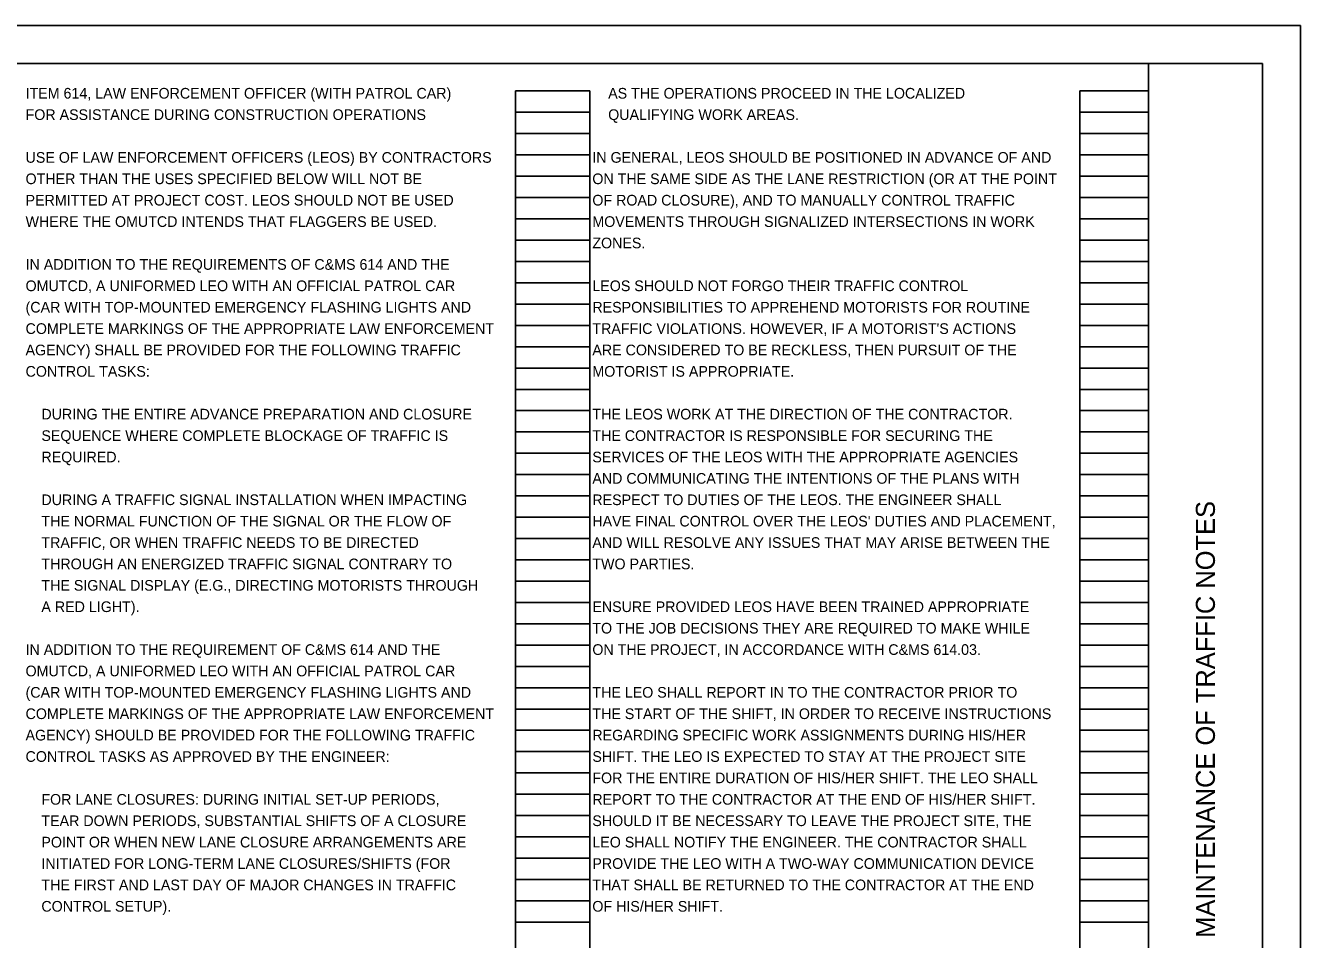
# Model space of a CAD drawing. Extents: x 0 to 34, y 0 to 22.
# Drawn here: x 17.24 to 34, y 9.99 to 22 of the extents above; entities that cross this region are included whole.
import ezdxf

# ---------------------------------------------------------------- set-up
doc = ezdxf.new("R2010")
doc.units = 0
for name, color, linetype in [('SH_Border', 7, 'Continuous'), ('SH_Cut_Line', 7, 'Continuous'), ('SH_Data', 7, 'Continuous'), ('TX_P_1', 7, 'Continuous')]:
    doc.layers.add(name, color=color, linetype=linetype)

msp = doc.modelspace()

# ---------------------------------------------------------------- linework, layer by layer
at = {"layer": 'SH_Border'}
msp.add_line((32, 0.5), (32, 21.5), dxfattribs=at)
msp.add_lwpolyline([(1.5, 21.5), (33.5, 21.5), (33.5, 0.5), (1.5, 0.5)], close=True, dxfattribs=at)
at = {"layer": 'SH_Cut_Line'}
msp.add_lwpolyline([(0, 0), (34, 0), (34, 22), (0, 22)], close=True, dxfattribs=at)
at = {"layer": 'SH_Data'}
for p, q in [((23.68, 0.98), (23.68, 21.14)), ((23.68, 21.14), (24.66, 21.14)), ((24.66, 0.98), (24.66, 21.14)), ((31.1, 0.98), (31.1, 21.14)), ((31.1, 21.14), (32, 21.14)), ((32, 0.98), (32, 21.14)), ((23.68, 20.86), (24.66, 20.86)), ((31.1, 20.86), (32, 20.86)), ((23.68, 20.58), (24.66, 20.58)), ((31.1, 20.58), (32, 20.58)), ((23.68, 20.3), (24.66, 20.3)), ((31.1, 20.3), (32, 20.3)), ((23.68, 20.02), (24.66, 20.02)), ((31.1, 20.02), (32, 20.02)), ((23.68, 19.74), (24.66, 19.74)), ((31.1, 19.74), (32, 19.74)), ((23.68, 19.46), (24.66, 19.46)), ((31.1, 19.46), (32, 19.46)), ((23.68, 19.18), (24.66, 19.18)), ((31.1, 19.18), (32, 19.18)), ((23.68, 18.9), (24.66, 18.9)), ((31.1, 18.9), (32, 18.9)), ((23.68, 18.62), (24.66, 18.62)), ((31.1, 18.62), (32, 18.62)), ((23.68, 18.34), (24.66, 18.34)), ((31.1, 18.34), (32, 18.34)), ((23.68, 18.06), (24.66, 18.06)), ((31.1, 18.06), (32, 18.06)), ((23.68, 17.78), (24.66, 17.78)), ((31.1, 17.78), (32, 17.78)), ((23.68, 17.5), (24.66, 17.5)), ((31.1, 17.5), (32, 17.5)), ((23.68, 17.22), (24.66, 17.22)), ((31.1, 17.22), (32, 17.22)), ((23.68, 16.94), (24.66, 16.94)), ((31.1, 16.94), (32, 16.94)), ((23.68, 16.66), (24.66, 16.66)), ((31.1, 16.66), (32, 16.66)), ((23.68, 16.38), (24.66, 16.38)), ((31.1, 16.38), (32, 16.38)), ((23.68, 16.1), (24.66, 16.1)), ((31.1, 16.1), (32, 16.1)), ((23.68, 15.82), (24.66, 15.82)), ((31.1, 15.82), (32, 15.82)), ((23.68, 15.54), (24.66, 15.54)), ((31.1, 15.54), (32, 15.54)), ((23.68, 15.26), (24.66, 15.26)), ((31.1, 15.26), (32, 15.26)), ((23.68, 14.98), (24.66, 14.98)), ((31.1, 14.98), (32, 14.98)), ((23.68, 14.7), (24.66, 14.7)), ((31.1, 14.7), (32, 14.7)), ((23.68, 14.42), (24.66, 14.42)), ((31.1, 14.42), (32, 14.42)), ((23.68, 14.14), (24.66, 14.14)), ((31.1, 14.14), (32, 14.14)), ((23.68, 13.86), (24.66, 13.86)), ((31.1, 13.86), (32, 13.86)), ((23.68, 13.58), (24.66, 13.58)), ((31.1, 13.58), (32, 13.58)), ((23.68, 13.3), (24.66, 13.3)), ((31.1, 13.3), (32, 13.3)), ((23.68, 13.02), (24.66, 13.02)), ((31.1, 13.02), (32, 13.02)), ((23.68, 12.74), (24.66, 12.74)), ((31.1, 12.74), (32, 12.74)), ((23.68, 12.46), (24.66, 12.46)), ((31.1, 12.46), (32, 12.46)), ((23.68, 12.18), (24.66, 12.18)), ((31.1, 12.18), (32, 12.18)), ((23.68, 11.9), (24.66, 11.9)), ((31.1, 11.9), (32, 11.9)), ((23.68, 11.62), (24.66, 11.62)), ((31.1, 11.62), (32, 11.62)), ((23.68, 11.34), (24.66, 11.34)), ((31.1, 11.34), (32, 11.34)), ((23.68, 11.06), (24.66, 11.06)), ((31.1, 11.06), (32, 11.06)), ((23.68, 10.78), (24.66, 10.78)), ((31.1, 10.78), (32, 10.78)), ((23.68, 10.5), (24.66, 10.5)), ((31.1, 10.5), (32, 10.5)), ((23.68, 10.22), (24.66, 10.22)), ((31.1, 10.22), (32, 10.22))]:
    msp.add_line(p, q, dxfattribs=at)

# ---------------------------------------------------------------- texts
msp.add_text('MAINTENANCE OF TRAFFIC NOTES', height=0.25, rotation=90, dxfattribs=at).set_placement((32.875, 10.014))
at = {"layer": 'TX_P_1'}
for s, p in [('ITEM 614, LAW ENFORCEMENT OFFICER (WITH PATROL CAR)', (17.242, 21.04)), ('    AS THE OPERATIONS PROCEED IN THE LOCALIZED', (24.692, 21.04)), ('FOR ASSISTANCE DURING CONSTRUCTION OPERATIONS', (17.242, 20.759)), ('    QUALIFYING WORK AREAS.', (24.692, 20.759)), ('USE OF LAW ENFORCEMENT OFFICERS (LEOS) BY CONTRACTORS', (17.242, 20.197)), ('IN GENERAL, LEOS SHOULD BE POSITIONED IN ADVANCE OF AND', (24.692, 20.197)), ('OTHER THAN THE USES SPECIFIED BELOW WILL NOT BE', (17.242, 19.916)), ('ON THE SAME SIDE AS THE LANE RESTRICTION (OR AT THE POINT', (24.692, 19.916)), ('PERMITTED AT PROJECT COST. LEOS SHOULD NOT BE USED', (17.242, 19.635)), ('OF ROAD CLOSURE), AND TO MANUALLY CONTROL TRAFFIC', (24.692, 19.635)), ('WHERE THE OMUTCD INTENDS THAT FLAGGERS BE USED.', (17.242, 19.354)), ('MOVEMENTS THROUGH SIGNALIZED INTERSECTIONS IN WORK', (24.692, 19.354)), ('ZONES.', (24.692, 19.073)), ('IN ADDITION TO THE REQUIREMENTS OF C&MS 614 AND THE', (17.242, 18.791)), ('OMUTCD, A UNIFORMED LEO WITH AN OFFICIAL PATROL CAR', (17.242, 18.51)), ('LEOS SHOULD NOT FORGO THEIR TRAFFIC CONTROL', (24.692, 18.51)), ('(CAR WITH TOP-MOUNTED EMERGENCY FLASHING LIGHTS AND', (17.242, 18.229)), ('RESPONSIBILITIES TO APPREHEND MOTORISTS FOR ROUTINE', (24.692, 18.229)), ('COMPLETE MARKINGS OF THE APPROPRIATE LAW ENFORCEMENT', (17.242, 17.948)), ("TRAFFIC VIOLATIONS. HOWEVER, IF A MOTORIST'S ACTIONS", (24.692, 17.948)), ('AGENCY) SHALL BE PROVIDED FOR THE FOLLOWING TRAFFIC', (17.242, 17.667)), ('ARE CONSIDERED TO BE RECKLESS, THEN PURSUIT OF THE', (24.692, 17.667)), ('CONTROL TASKS:', (17.242, 17.386)), ('MOTORIST IS APPROPRIATE.', (24.692, 17.386)), ('    DURING THE ENTIRE ADVANCE PREPARATION AND CLOSURE', (17.242, 16.824)), ('THE LEOS WORK AT THE DIRECTION OF THE CONTRACTOR.', (24.692, 16.824)), ('    SEQUENCE WHERE COMPLETE BLOCKAGE OF TRAFFIC IS', (17.242, 16.542)), ('THE CONTRACTOR IS RESPONSIBLE FOR SECURING THE', (24.692, 16.542)), ('    REQUIRED.', (17.242, 16.261)), ('SERVICES OF THE LEOS WITH THE APPROPRIATE AGENCIES', (24.692, 16.261)), ('AND COMMUNICATING THE INTENTIONS OF THE PLANS WITH', (24.692, 15.98)), ('    DURING A TRAFFIC SIGNAL INSTALLATION WHEN IMPACTING', (17.242, 15.699)), ('RESPECT TO DUTIES OF THE LEOS. THE ENGINEER SHALL', (24.692, 15.699)), ('    THE NORMAL FUNCTION OF THE SIGNAL OR THE FLOW OF', (17.242, 15.418)), ("HAVE FINAL CONTROL OVER THE LEOS' DUTIES AND PLACEMENT,", (24.692, 15.418)), ('    TRAFFIC, OR WHEN TRAFFIC NEEDS TO BE DIRECTED', (17.242, 15.137)), ('AND WILL RESOLVE ANY ISSUES THAT MAY ARISE BETWEEN THE', (24.692, 15.137)), ('    THROUGH AN ENERGIZED TRAFFIC SIGNAL CONTRARY TO', (17.242, 14.856)), ('TWO PARTIES.', (24.692, 14.856)), ('    THE SIGNAL DISPLAY (E.G., DIRECTING MOTORISTS THROUGH', (17.242, 14.575)), ('    A RED LIGHT).', (17.242, 14.294)), ('ENSURE PROVIDED LEOS HAVE BEEN TRAINED APPROPRIATE', (24.692, 14.294)), ('TO THE JOB DECISIONS THEY ARE REQUIRED TO MAKE WHILE', (24.692, 14.012)), ('IN ADDITION TO THE REQUIREMENT OF C&MS 614 AND THE', (17.242, 13.731)), ('ON THE PROJECT, IN ACCORDANCE WITH C&MS 614.03.', (24.692, 13.731)), ('OMUTCD, A UNIFORMED LEO WITH AN OFFICIAL PATROL CAR', (17.242, 13.45)), ('(CAR WITH TOP-MOUNTED EMERGENCY FLASHING LIGHTS AND', (17.242, 13.169)), ('THE LEO SHALL REPORT IN TO THE CONTRACTOR PRIOR TO', (24.692, 13.169)), ('COMPLETE MARKINGS OF THE APPROPRIATE LAW ENFORCEMENT', (17.242, 12.888)), ('THE START OF THE SHIFT, IN ORDER TO RECEIVE INSTRUCTIONS', (24.692, 12.888)), ('AGENCY) SHOULD BE PROVIDED FOR THE FOLLOWING TRAFFIC', (17.242, 12.607)), ('REGARDING SPECIFIC WORK ASSIGNMENTS DURING HIS/HER', (24.692, 12.607)), ('CONTROL TASKS AS APPROVED BY THE ENGINEER:', (17.242, 12.326)), ('SHIFT. THE LEO IS EXPECTED TO STAY AT THE PROJECT SITE', (24.692, 12.326)), ('FOR THE ENTIRE DURATION OF HIS/HER SHIFT. THE LEO SHALL', (24.692, 12.045)), ('    FOR LANE CLOSURES: DURING INITIAL SET-UP PERIODS,', (17.242, 11.763)), ('REPORT TO THE CONTRACTOR AT THE END OF HIS/HER SHIFT.', (24.692, 11.763)), ('    TEAR DOWN PERIODS, SUBSTANTIAL SHIFTS OF A CLOSURE', (17.242, 11.482)), ('SHOULD IT BE NECESSARY TO LEAVE THE PROJECT SITE, THE', (24.692, 11.482)), ('    POINT OR WHEN NEW LANE CLOSURE ARRANGEMENTS ARE', (17.242, 11.201)), ('LEO SHALL NOTIFY THE ENGINEER. THE CONTRACTOR SHALL', (24.692, 11.201)), ('    INITIATED FOR LONG-TERM LANE CLOSURES/SHIFTS (FOR', (17.242, 10.92)), ('PROVIDE THE LEO WITH A TWO-WAY COMMUNICATION DEVICE', (24.692, 10.92)), ('    THE FIRST AND LAST DAY OF MAJOR CHANGES IN TRAFFIC', (17.242, 10.639)), ('THAT SHALL BE RETURNED TO THE CONTRACTOR AT THE END', (24.692, 10.639)), ('    CONTROL SETUP).', (17.242, 10.358)), ('OF HIS/HER SHIFT.', (24.692, 10.358))]:
    msp.add_text(s, height=0.14, dxfattribs=at).set_placement(p)

doc.saveas('drawing.dxf')
